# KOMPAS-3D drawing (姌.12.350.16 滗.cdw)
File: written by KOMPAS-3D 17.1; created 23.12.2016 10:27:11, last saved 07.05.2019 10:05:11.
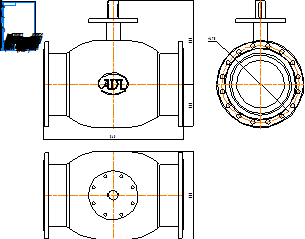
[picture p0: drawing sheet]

Sheet 1: A4, portrait

Title block, sheet 1: name: КШ.12.350.16 фф; material: Внимание! Данный продукт является объектом авторского права ООО «Торговый Дом АДЛ». / Запрещается изменение, копирование, распространение / (в том числе путем копирования на другие сайты и ресурсы в Интернете) / или любое иное использование информации и объектов без предварительного / согласия правообладателя (ООО «Торговый Дом АДЛ»).; sheets: 1; organisation: ООО "Торговый дом АДЛ"; sheet format: A4; stored path: C:\Users\tra\Desktop\2д чертежи\Шаровые краны БИВАЛ\КШ_Бивал_серия_11_12\KOMPAS_2D\КШ.12.350.16 фф.cdw

Views: Вид 1, Проекционный вид 2, Проекционный вид 3
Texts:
  Klimkovich
  ADL
Dimensions and other numbers on the sheet: 848; 505; 260; 470; 530; 1:1; 1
